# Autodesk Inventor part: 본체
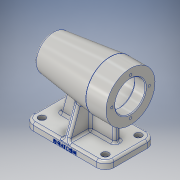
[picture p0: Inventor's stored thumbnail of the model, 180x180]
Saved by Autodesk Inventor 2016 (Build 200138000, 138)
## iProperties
Created: 2018-09
Part Number: 본체
Material: 알루미늄 6061
Document SubType Name: Modeling
Designer: CAMTIC
Mass: 732.752 g
Surface Area: 663.622 cm^2
Volume: 271.389 cm^3
Density: 2.7 g/cm^3
Appearance: 알루미늄 - 평지
Author: CAMTIC
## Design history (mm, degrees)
sketch "스케치1"
  geometry: L1 (56, -35)-(-56, -35); L2 (-56, -35)-(-56, 35); L3 (-56, 35)-(56, 35); L4 (56, 35)-(56, -35); L5 (56, -35)-(-56, 35); L6 (-56, -35)-(56, 35); 2 further points
  constraints: 12 end point, 4 midpoint, 2 parallel, 1 horizontal, 1 perpendicular
  dimensions: "d0" = 112 distance of L1.start L1.end; "d1" = 70 distance of L1.end L2.end
extrude "돌출1" new body sketch "스케치1" distance "d2" = 10; taper "d3" = 0 deg
revolve "회전1" stored, may be unused: angle "d11" = 90 deg
fillet "모깎기1" dims "d12" = 3
revolve "회전2" stored, may be unused: angle "d28" = 90 deg
chamfer "모따기1" distance "d29" = 1; stored, may be unused: second distance "d30" = 2, angle "d31" = 45 deg
fillet "모깎기2" dims "d32" = 12
fillet "모깎기3" dims "d33" = 3
sketch "스케치4"
  geometry: L1 (-21.6, 0)-(129.6, 0) reference; L2 (0, -49.87)-(0, 49.87) reference; L3 (8.026, 34.819)-(54.34, 17.962); L4 (7, 35)-(0, 35) reference; L5 (0, -35)-(7, -35) reference; L6 (8.026, -34.819)-(54.34, -17.962); L7 (10, 32)-(10, 23) reference; L8 (10, -23)-(10, 23) reference; L9 (10, -23)-(10, -32) reference; C1 r 34 at (74, 0) reference; C2 r 7.5 at (74, 0) reference; A1 r 3 centre (7, 32) between (10, 32) and (7, 35) reference; A2 r 3 centre (7, -32) between (7, -35) and (10, -32) reference; A3 r 26.63 centre (74, 0) between (54.34, 17.962) and (54.34, -17.962); 1 further point
  constraints: 4 end point, 4 point on circle, 2 tangent, 1 centre point, 1 coincident
  dimensions: "d34" = 20 deg angle of L4 L3; "d36" = 20 deg angle of L5 L6; "d37" = 26.62958 radius of A3
extrude "돌출2" join sketch "스케치4" stored distance "d38" = 8; taper "d39" = 0 deg
sketch "스케치5"
  geometry: L1 (4, 4)-(4, -4); L2 (4, -4)-(38, -4); L3 (38, -4)-(38, 4); L4 (38, 4)-(4, 4); L5 (-38, -4)-(-4, -4); L6 (-4, -4)-(-4, 4); L7 (-4, 4)-(-38, 4); L8 (-38, 4)-(-38, -4); L9 (4, 32)-(4, -32) reference; L10 (0, 49)-(0, -49) reference; L11 (78.4, 0)-(-78.4, 0) reference; L12 (56, -34)-(56, 34) reference; L13 (-4, -32)-(-4, 32) reference; L14 (-56, 23)-(-56, -23) reference; 1 further point
  constraints: 16 end point, 4 perpendicular, 2 collinear, 2 parallel, 1 horizontal, 1 vertical
  dimensions: "d40" = 4 distance between parallel lines of L11 L2; "d41" = 8 distance of L2.end L3.end; "d42" = 18 distance between parallel lines of L12 L3; "d43" = 8 distance of L7.end L5.start; "d44" = 4 distance between parallel lines of L11 L7; "d45" = 18 distance between parallel lines of L8 L14
extrude "돌출3" join sketch "스케치5" stored distance "d46" = 8; taper "d47" = 0 deg
feature "면 기울기1" dims angle "d48" = 15 deg
hole "구멍1" diameter "d51" = 9.5; stored, may be unused: countersink angle "d55" = 90 deg, drill point angle "d57" = 0 deg; dims "d49" = 10, "d50" = 10, "d52" = 6, "d53" = 4, "d54" = 2, "d56" = 5.4
hole "구멍2" diameter "d60" = 5.5; stored, may be unused: countersink angle "d64" = 90 deg, drill point angle "d66" = 0 deg; dims "d58" = 10, "d59" = 10, "d61" = 6, "d62" = 4, "d63" = 2, "d65" = 5.4
sketch "스케치6"
  geometry: L1 (0, -95.6)-(0, 55.6) reference; L2 (49, -74)-(-49, -74) reference; 2 further points
  constraints: 1 point on line
  dimensions: "d73" = 100 distance from line of L2 point (0, 26)
hole "구멍3" sketch "스케치6" at (0, 26) diameter "d74" = 3.242; stored, may be unused: countersink angle "d78" = 90 deg, drill point angle "d80" = 118 deg; dims "d75" = 8, "d76" = 4, "d77" = 2, "d79" = 11
fillet "모깎기4" dims "d84" = 3
fillet "모깎기5" dims "d85" = 3
fillet "모깎기6" dims "d86" = 3
sketch "스케치7"
  geometry: L1 (44, -21.6)-(44, 129.6) reference; L2 (-34.4, 0)-(122.4, 0) reference; L3 (100, 0)-(100, 7) reference; 2 further points
  constraints: 1 other
  dimensions: "d87" = 3 distance from line of L2 point (44, 3); "d88" = 56 distance from line of L3 point (44, 3)
feature "엠보싱1" sketch "스케치7" dims "d0" = 112, "d1" = 70, "d89" = 0.5, "d90" = 0
node "솔리드1"
pattern_linear "직사각형 패턴1" dims "d69" = 88, "d72" = 46
pattern_circular "원형 패턴1" dims angle "d82" = 360 deg
sketch "스케치2"
  geometry: L1 (-87.378, 74)-(86.477, 74); L2 (0, 129.6)-(0, -21.6) reference; L3 (-122.149, 0)-(121.248, 0) reference; L4 (56, 74)-(56, 108); L5 (56, 108)-(28, 108); L6 (28, 108)-(-52.27, 98.144); L7 (-56, 91.74)-(-56, 32.333); L8 (56, 0)-(56, 10) reference; L9 (-56, 74)-(56, 74); A1 r 80 centre (24, 74) between (-52.27, 98.144) and (-56, 74); 1 further point
  constraints: 12 end point, 3 point on line, 2 collinear, 2 point on circle, 2 vertical, 1 centre point, 1 horizontal, 1 perpendicular, 1 tangent
  dimensions: "d4" = 74 distance between parallel lines of L3 L1; "d6" = 34 distance of L4.start L4.end; "d7" = 28 distance of L4.end L5.end; "d8" = 112 distance between parallel lines of L4 L7; "d9" = 7 deg angle of L5 L6; "d10" = 80 radius of A1
sketch "스케치3"
  geometry: L1 (-88.279, 74)-(104.793, 74); L2 (0, 129.6)-(0, -21.6) reference; L3 (-126.893, 0)-(143.408, 0) reference; L4 (56, 95)-(41, 95); L5 (41, 95)-(41, 95); L6 (38, 98)-(-10, 98); L7 (-13, 95)-(-13, 95); L8 (-13, 95)-(-24.7, 95); L9 (-25, 94.7)-(-25, 91.5); L10 (-25, 91.5)-(-42.7, 91.5); L11 (-43, 91.2)-(-43, 90); L12 (-43, 90)-(-46.7, 90); L13 (-47, 89.7)-(-47, 84.5); L14 (-47, 84.5)-(-47, 84.5); L15 (-50, 81.5)-(-50, 74); L16 (56, 74)-(56, 95); L17 (56, 40)-(56, 108) reference; L18 (56, 74)-(-50, 74); A1 r 3 centre (-47, 81.5) between (-47, 84.5) and (-50, 81.5); A2 r 0.3 centre (-46.7, 89.7) between (-46.7, 90) and (-47, 89.7); A3 r 0.3 centre (-42.7, 91.2) between (-42.7, 91.5) and (-43, 91.2); A4 r 0.3 centre (-24.7, 94.7) between (-24.7, 95) and (-25, 94.7); A5 r 3 centre (-10, 95) between (-10, 98) and (-13, 95); A6 r 3 centre (38, 95) between (41, 95) and (38, 98); 5 further points
  constraints: 30 end point, 12 point on circle, 12 point on line, 12 tangent, 10 perpendicular, 6 centre point, 3 collinear, 3 equal radius, 2 horizontal
  dimensions: "d13" = 74 distance between parallel lines of L3 L1; "d14" = 21 distance of L16.start L4.start; "d15" = 24 distance between parallel lines of L18 L6; "d16" = 15 distance between parallel lines of L16 L5; "d17" = 54 distance between parallel lines of L5 L7; "d18" = 12 distance of L7.end point (-25, 95); "d19" = 18 distance of L9.end point (-43, 91.5); "d20" = 4 distance of L11.end point (-47, 90); "d21" = 3 distance of L13.end point (-50, 84.5); "d22" = 17.5 distance between parallel lines of L18 L10; "d23" = 16 distance between parallel lines of L18 L12; "d24" = 10.5 distance between parallel lines of L18 L14; "d25" = 3 radius of A1; "d26" = 0.3 radius of A2; "d27" = 3 radius of A5
other parameters: "d35" = 20 deg
